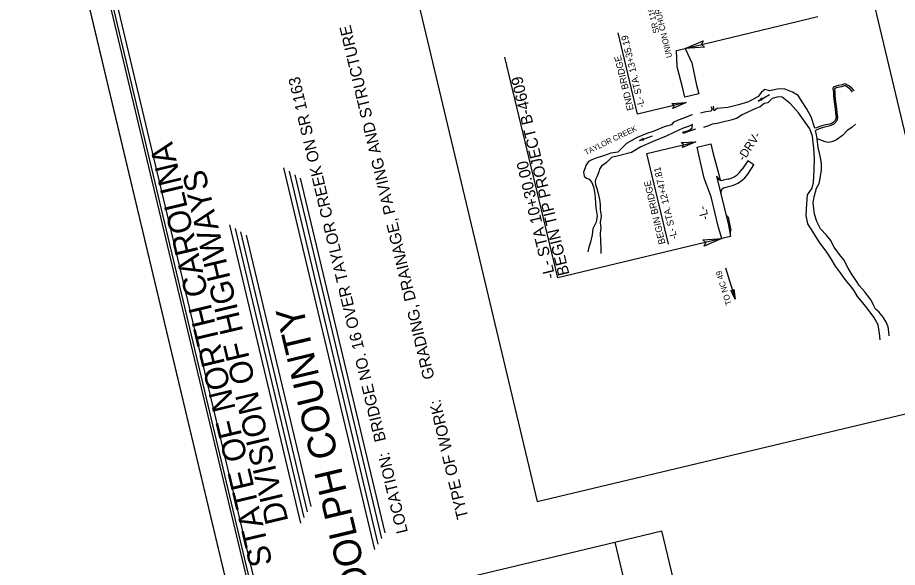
# Model space of a CAD drawing. Extents: x 1734738 to 1742883, y 698103 to 703125.
# Drawn here: x 1734738 to 1736650, y 699508 to 700702 of the extents above; entities that cross this region are included whole.
import ezdxf

# ---------------------------------------------------------------- set-up
doc = ezdxf.new("R2010")
doc.units = 0
for name, color, linetype in [('Default', 7, 'Continuous'), ('Exist Cultural Recreational Athletic Track', 7, 'Continuous'), ('Exist Map Preparation Border Sheet 1 CELL', 7, 'Continuous'), ('Exist Road Primary US Shield CELL', 7, 'Continuous'), ('Exist Road Primary US Structure Standard Bridge Number Label', 7, 'Continuous'), ('Exist Road Secondary Mileage Hundredths English Label', 7, 'Continuous'), ('Exist Road Secondary Structure Culvert Number Label', 7, 'Continuous'), ('Exist Road Secondary Structure Pipe Number Label', 7, 'Continuous'), ('Exist Road Secondary Type 41 Number Label', 7, 'Continuous'), ('Exist Road Secondary Type 41 SR Number Label', 7, 'Continuous'), ('Exist Road Secondary Type 51 Divided Label', 7, 'Continuous'), ('Exist Road Secondary Type 51 Undivided 3 Lane Attributed', 7, 'Continuous'), ('Level 54', 7, 'Continuous'), ('Level 55', 7, 'Continuous'), ('Level 57', 7, 'Continuous')]:
    doc.layers.add(name, color=color, linetype=linetype)

# ---------------------------------------------------------------- blocks, each defined once
blk = doc.blocks.new('EXIST HYDRO STREAM FLOW ARROW')
at = {"layer": 'Default'}
blk.add_line((0, 0), (0, 0), dxfattribs=at)
for points in [[(-0.1, 0.04575), (-0.07325, 0.03375), (-0.04475, 0.0245), (-0.0165, 0.01575), (0.01175, 0.0095), (0.041, 0.00475), (0.07075, 0.0015), (0.1, 0)], [(-0.1, -0.04575), (-0.07325, -0.03375), (-0.04475, -0.0245), (-0.0165, -0.01575), (0.01175, -0.0095), (0.041, -0.00475), (0.07075, -0.0015), (0.1, 0)]]:
    blk.add_lwpolyline(points, dxfattribs=at)

msp = doc.modelspace()

# ---------------------------------------------------------------- linework, layer by layer
at = {"layer": 'Exist Cultural Recreational Athletic Track'}
for p, q in [((1736188.7, 700634.5), (1736477, 700703.7)), ((1736085.2, 700491.6), (1736042.7, 700668.7)), ((1735912.1, 700136.2), (1735797, 700616)), ((1736190.9, 700516.9), (1736085.2, 700491.6)), ((1736152.6, 700209.8), (1736105.4, 700406.6)), ((1736268.4, 700221.7), (1735912.1, 700136.2)), ((1736276.5, 700158.5), (1736297.4, 700090.4))]:
    msp.add_line(p, q, dxfattribs=at)
at = {"layer": 'Exist Road Primary US Shield CELL'}
msp.add_lwpolyline([(1735867.2, 699650.6), (1736804.2, 699873.9), (1736485.1, 701212.6), (1735736.8, 701034.2), (1735787.7, 700820.7), (1735599, 700775.7)], close=True, dxfattribs=at)
at = {"layer": 'Exist Road Primary US Structure Standard Bridge Number Label'}
msp.add_line((1735518.8, 698102.6), (1734738, 701378.8), dxfattribs=at)
at = {"layer": 'Exist Road Secondary Mileage Hundredths English Label'}
for points in [[(1736556, 700542.9), (1736556, 700542.9), (1736551.3, 700547.4), (1736543.9, 700553.3), (1736537.8, 700557.2), (1736534.9, 700557.5), (1736529.4, 700555.7), (1736522, 700553.9), (1736516.7, 700553), (1736510.3, 700550.6), (1736509.5, 700546.8), (1736510.6, 700539.9), (1736510.7, 700532.1), (1736511.9, 700524.3), (1736513.2, 700513.6), (1736514.6, 700503.8), (1736515.4, 700494.8), (1736516.4, 700484.4), (1736514.8, 700477.9), (1736510.2, 700474.1), (1736503, 700470.4), (1736494.2, 700468.9), (1736485.6, 700466.5), (1736478.8, 700464.3), (1736473.7, 700462.3)], [(1736537.1, 700553.4), (1736537.1, 700553.4), (1736534.2, 700553.4), (1736528.2, 700550.9), (1736524.4, 700550.3), (1736520.4, 700549.7), (1736516.8, 700549.1), (1736513.8, 700547.7)], [(1736552.3, 700539.7), (1736547.5, 700545.2), (1736541.9, 700549.8), (1736537.1, 700553.4)], [(1736513.8, 700547.7), (1736513.3, 700545.1), (1736513.6, 700540.4), (1736513.9, 700532.6), (1736514.8, 700524.8), (1736516.1, 700514), (1736517.5, 700504.2), (1736518.3, 700494.8), (1736519.2, 700484.8), (1736518.2, 700477.7), (1736512.2, 700470.9), (1736503.8, 700466.9), (1736494.9, 700464.4), (1736486.3, 700462.4), (1736479.5, 700460.2)], [(1736473.7, 700462.3), (1736470.3, 700461.8)], [(1736479.5, 700460.2), (1736471.6, 700456.3)], [(1736559, 700470.1), (1736550.4, 700463.1), (1736540.9, 700456.4), (1736530.4, 700445.4), (1736517.1, 700435.9), (1736509.4, 700432.7), (1736500.5, 700430.6), (1736497.4, 700430.8), (1736493, 700432)], [(1736493, 700432), (1736475.1, 700438.1)]]:
    msp.add_lwpolyline(points, dxfattribs=at)
at = {"layer": 'Exist Road Secondary Structure Culvert Number Label'}
for p, q in [((1736105.4, 700406.6), (1736211.5, 700432)), ((1736035.6, 699562.3), (1736138, 699586.7)), ((1736326.6, 698795.4), (1736138, 699586.7))]:
    msp.add_line(p, q, dxfattribs=at)
msp.add_lwpolyline([(1735551.6, 698610.7), (1735363, 699402), (1736035.6, 699562.3), (1736224.2, 698771)], close=True, dxfattribs=at)
at = {"layer": 'Exist Road Secondary Structure Pipe Number Label'}
msp.add_lwpolyline([(1737609.2, 698627.6), (1736836.4, 701869.7), (1734783.7, 701380.5), (1735556.5, 698138.3)], close=True, dxfattribs=at)
at = {"layer": 'Exist Road Secondary Type 41 Number Label'}
for points in [[(1736230.5, 700637.1), (1736188.7, 700634.5), (1736227.4, 700651.2), (1736223.9, 700642.9)], [(1736159.5, 700514.9), (1736190.9, 700516.9), (1736161.9, 700504.3), (1736164.4, 700510.6)], [(1736180.2, 700430), (1736211.5, 700432), (1736182.5, 700419.4), (1736185.1, 700425.7)], [(1736226.6, 700219.2), (1736268.4, 700221.7), (1736229.7, 700205), (1736233.1, 700213.4)], [(1736294.6, 700111.2), (1736297.4, 700090.4), (1736287.7, 700109.1), (1736292, 700107.7)]]:
    msp.add_lwpolyline(points, close=True, dxfattribs=at)
at = {"layer": 'Exist Road Secondary Type 41 SR Number Label'}
msp.add_lwpolyline([(1734738, 701378.8), (1735518.8, 698102.6), (1737658.8, 698612.7), (1736878, 701888.9)], close=True, dxfattribs=at)
at = {"layer": 'Exist Road Secondary Type 51 Divided Label'}
for p, q in [((1735514.2, 699546.4), (1735316.7, 700375.2)), ((1735521.6, 699558.4), (1735328.8, 700367.8)), ((1735529.1, 699570.5), (1735340.8, 700360.4)), ((1735536.5, 699582.5), (1735352.9, 700353)), ((1735353.3, 699604), (1735199, 700251.3)), ((1735360.7, 699616), (1735211.1, 700243.9)), ((1735368.1, 699628), (1735223.1, 700236.5)), ((1735375.6, 699640.1), (1735235.1, 700229.1))]:
    msp.add_line(p, q, dxfattribs=at)
for points in [[(1734799.1, 701337.9), (1735485.4, 698458.5)], [(1734811.2, 701330.5), (1735469.6, 698567.9)]]:
    msp.add_lwpolyline(points, dxfattribs=at)
at = {"layer": 'Exist Road Secondary Type 51 Undivided 3 Lane Attributed'}
for p, q in [((1735435.9, 700215.7), (1735435.9, 700215.7)), ((1735385.8, 699956.9), (1735385.8, 699956.9))]:
    msp.add_line(p, q, dxfattribs=at)
at = {"layer": 'Level 54'}
for p, q in [((1736347, 700520), (1736372.1, 700534.8)), ((1736089.9, 700434.6), (1736117.2, 700444.9))]:
    msp.add_line(p, q, dxfattribs=at)
at = {"layer": 'Level 55'}
for points in [[(1736361.5, 700545.4), (1736354.5, 700539.6), (1736347.1, 700530.2), (1736326.5, 700519), (1736304.3, 700512.3), (1736280.9, 700506.6), (1736258.2, 700504.5), (1736251.2, 700499), (1736250, 700509.5)], [(1736470.3, 700461.8), (1736462.3, 700486.1), (1736452.3, 700504), (1736442.6, 700518.8), (1736433.9, 700532.5), (1736421.8, 700539.7), (1736403.6, 700546.6), (1736388.1, 700546.3), (1736372.5, 700542.2), (1736361.5, 700545.4)], [(1736229.3, 700463.7), (1736239.8, 700467.3), (1736248.2, 700470.7), (1736257.8, 700472.2), (1736275.2, 700476.7), (1736288.6, 700479.9), (1736299.8, 700483.4), (1736312.7, 700491.1), (1736322.8, 700495.6), (1736337.8, 700502.9), (1736351.4, 700508.8), (1736360.1, 700515.9), (1736368.8, 700517.5)], [(1736612.3, 700001.7), (1736610.6, 700015.4), (1736607.8, 700034.2), (1736598.6, 700051.2), (1736586.3, 700067.8), (1736571.7, 700085.6), (1736563.3, 700096.2), (1736555.3, 700109.9), (1736547.6, 700119.1), (1736536.4, 700132.8), (1736526.2, 700147.1), (1736515.3, 700162.1), (1736506, 700177.6), (1736496.3, 700192.3), (1736479.4, 700214.8), (1736466.7, 700235.3), (1736454.8, 700253.6), (1736451.4, 700271.5), (1736453.1, 700297.3), (1736454.3, 700316.4), (1736464.5, 700331.3), (1736467.7, 700343.8), (1736468.8, 700371.2), (1736469.6, 700395.8), (1736468, 700417.8), (1736465, 700444.4), (1736459.6, 700460), (1736445.6, 700479.9), (1736435.1, 700494.5), (1736417.3, 700514.6), (1736399.2, 700529), (1736390.5, 700529.6), (1736377.8, 700525.9), (1736368.8, 700517.5)], [(1736244.1, 700508.3), (1736246.9, 700503.1), (1736245.2, 700498.5), (1736233.4, 700496.7), (1736221.9, 700493.9)], [(1736203.4, 700490.2), (1736183.8, 700482.6), (1736173.5, 700479.1), (1736162.2, 700473.5), (1736158.9, 700468.5), (1736142.6, 700464.4), (1736119, 700454), (1736105.1, 700450.2), (1736084, 700441.5), (1736060.8, 700428.4)], [(1736203.2, 700490.1), (1736183.8, 700482.6), (1736173.5, 700479.1), (1736162.2, 700473.5), (1736158.9, 700468.5), (1736142.6, 700464.4), (1736119, 700454), (1736105.1, 700450.2), (1736084, 700441.5), (1736060.8, 700428.4)], [(1736210.7, 700459.6), (1736195.5, 700454.3), (1736185, 700450.2), (1736183.7, 700452.6), (1736195.7, 700456.3), (1736203.5, 700461.3), (1736203.5, 700464.5), (1736204.5, 700469.4), (1736197.5, 700465.5), (1736184, 700461.7), (1736165.3, 700452.7), (1736147.3, 700443.8), (1736118.7, 700432.5), (1736092.2, 700420.6), (1736072.1, 700408.9)], [(1736466.9, 700299.5), (1736468.8, 700312.3), (1736473.9, 700331.5), (1736479.4, 700341.5), (1736482.6, 700356.5), (1736485, 700371.2), (1736484.9, 700384), (1736482.6, 700398), (1736477.9, 700419.4), (1736475.1, 700438.1), (1736473.7, 700447), (1736471.6, 700456.3)], [(1736060.8, 700428.4), (1736042.5, 700409.6), (1736027.2, 700407.1), (1736010.9, 700401.4), (1735996.6, 700397.4), (1735985.6, 700392.9), (1735978.3, 700389), (1735972.8, 700380.3), (1735971, 700375.4), (1735967.9, 700365.8)], [(1736072.1, 700408.9), (1736043.8, 700401.1), (1736028.7, 700397.9), (1736017.7, 700387.2), (1736007.1, 700379), (1736002.3, 700372.1), (1736000.8, 700366.6)], [(1735967.9, 700365.8), (1735967.9, 700365.8), (1735968.6, 700361.5), (1735969.3, 700356.9), (1735974.1, 700353.1), (1735980.3, 700350.8), (1735985.9, 700343.3), (1735989.6, 700333.9), (1735991.4, 700322.5), (1735993.2, 700311.2), (1735993.6, 700297.6), (1735994.3, 700288.3), (1735995.6, 700280), (1735997, 700270.9), (1735995.4, 700257.6), (1735988.2, 700243), (1735986.7, 700229.9), (1735982.7, 700214.2), (1735979.5, 700202.7), (1735977, 700193.1)], [(1736000.8, 700366.6), (1736000.8, 700366.6), (1735997.6, 700357.5), (1735993.6, 700350.1), (1735992.9, 700345.2), (1735993.9, 700339.5), (1735996.4, 700330.4), (1735999.7, 700319.3), (1736002.3, 700306.4), (1736004, 700295.7), (1736004.2, 700284), (1736005.2, 700276.5), (1736006.2, 700270.3), (1736004.2, 700256.5), (1736005.2, 700244.1), (1736004.2, 700233.7), (1736004.4, 700216.2), (1736005.3, 700200.2), (1736005.2, 700189.4)], [(1736585.7, 700097.3), (1736585.7, 700097.3), (1736578.7, 700106.2), (1736567.6, 700119.4), (1736561.2, 700129.4), (1736551.3, 700142.9), (1736542.7, 700157.6), (1736533.3, 700175.7), (1736524.1, 700187.1), (1736512.6, 700203.2), (1736504.6, 700217.9), (1736496, 700229.3), (1736482.7, 700243.1), (1736474.9, 700258.6), (1736469.8, 700274.4), (1736467.9, 700286.3), (1736466.9, 700299.5)], [(1736632, 700010.6), (1736631.2, 700019.4), (1736629.5, 700030.1), (1736625, 700040.1), (1736618.7, 700051.2), (1736609.7, 700062.8), (1736602.1, 700068.6), (1736598.3, 700076), (1736592.4, 700088.3), (1736585.7, 700097.3)]]:
    msp.add_lwpolyline(points, dxfattribs=at)
at = {"layer": 'Level 57'}
for p, q in [((1736324.8, 700390.4), (1736312.7, 700372.4)), ((1736338.1, 700381.6), (1736324.8, 700390.4)), ((1736326, 700363.5), (1736338.1, 700381.6)), ((1736264.4, 700348.7), (1736256.9, 700357.1)), ((1736281.8, 700350.8), (1736271.4, 700348.3)), ((1736275.2, 700332.7), (1736285.6, 700335.2)), ((1736287, 700246.8), (1736283, 700268)), ((1736288.2, 700240.8), (1736287, 700246.8)), ((1736287.7, 700240.1), (1736288.2, 700240.8))]:
    msp.add_line(p, q, dxfattribs=at)
for points in [[(1736188.7, 700634.5), (1736203, 700603.4), (1736213.5, 700554.6), (1736218, 700535.9), (1736188, 700528.6), (1736183.5, 700547.3), (1736183.5, 700547.3), (1736171.4, 700594.7), (1736171, 700595.8), (1736169.9, 700630)], [(1736268.4, 700221.7), (1736261.3, 700245.7), (1736245.2, 700312.1), (1736229.7, 700352.8), (1736218.4, 700403.8), (1736214.3, 700420.3), (1736244.3, 700427.6), (1736248.8, 700408.9), (1736248.8, 700408.9), (1736261.6, 700360.6), (1736264.5, 700348.6), (1736264.4, 700348.7), (1736256.9, 700357.1), (1736265.4, 700321.9), (1736282.7, 700250.9), (1736282.7, 700250.9), (1736287.4, 700226.3)]]:
    msp.add_lwpolyline(points, close=True, dxfattribs=at)
for points in [[(1736256.9, 700357.1), (1736265.4, 700321.9), (1736266.3, 700318.2)], [(1736276.8, 700275), (1736282.7, 700250.9), (1736286.2, 700232.6)]]:
    msp.add_lwpolyline(points, dxfattribs=at)
for centre, radius, start, end in [((1736269.5, 700401.3), 52, 283.6519, 326.2194), ((1736269.5, 700401.3), 68, 283.6519, 326.2194), ((1736268.5, 700359.9), 12, 193.6519, 249.527), ((1736268.5, 700359.9), 12, 193.6519, 283.6519), ((1736278, 700321.1), 12, 103.6519, 193.6519), ((1736286.5, 700277.3), 10, 193.6519, 249.4963), ((1736296, 700234.5), 10, 146.4515, 190.9706)]:
    msp.add_arc(centre, radius, start, end, dxfattribs=at)

# ---------------------------------------------------------------- block references
at = {"layer": 'Level 54', "yscale": 49.99999999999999}
for p, xscale, rotation in [((1736351.3, 700522.5), 49.999999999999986, -149.1137213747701), ((1736093.5, 700435.9), 50, -159.12784213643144)]:
    msp.add_blockref('EXIST HYDRO STREAM FLOW ARROW', p, dxfattribs=dict(at, xscale=xscale, rotation=rotation))

# ---------------------------------------------------------------- texts
at = {"layer": 'Exist Cultural Recreational Athletic Track'}
for s, height, rotation, p in [('UNION CHURCH RD', 12.844, 103.4845, (1736160.4, 700615.9)), ('SR 1163', 12.84, 103.4845, (1736132.3, 700669.1)), ('-L- STA. 13+35.19', 14.679, 103.4845, (1736100.9, 700507.9)), ('END BRIDGE', 14.68, 103.4845, (1736076.9, 700501.6)), ('BEGIN TIP PROJECT B-4609', 24.771, 103.4845, (1735937.2, 700144.5)), ('-DRV-', 18.35, 57.1569, (1736316.6, 700388.7)), ('-L- STA 10+30.00', 24.771, 103.4845, (1735906.8, 700137.3)), ('-L- STA. 12+47.81', 14.679, 103.4845, (1736171.6, 700222.1)), ('BEGIN BRIDGE', 14.679, 103.4845, (1736145.9, 700211.1)), ('-L-', 18.35, 103.4797, (1736240.2, 700265)), ('TO NC 49', 12.84, 107.0772, (1736289.7, 700079.3))]:
    msp.add_text(s, height=height, rotation=rotation, dxfattribs=at).set_placement(p)
at = {"layer": 'Exist Map Preparation Border Sheet 1 CELL'}
for s, height, p in [('GRADING, DRAINAGE, PAVING AND STRUCTURE ', 25, (1735644.3, 699919.2)), ('BRIDGE NO. 16 OVER TAYLOR CREEK ON SR 1163 ', 25, (1735538.8, 699783.5)), ('       RANDOLPH COUNTY       ', 60, (1735579.7, 699143.2))]:
    msp.add_text(s, height=height, rotation=103.4059, dxfattribs=at).set_placement(p)
at = {"layer": 'Exist Road Secondary Type 51 Divided Label'}
for s, height, p in [('STATE OF NORTH CAROLINA', 50, (1735292.2, 699515.8)), ('DIVISION OF HIGHWAYS', 50, (1735326.7, 699608.1)), ('TYPE OF WORK:', 25, (1735717.6, 699615.8)), ('LOCATION: ', 25, (1735586.2, 699584.5))]:
    msp.add_text(s, height=height, rotation=103.4059, dxfattribs=at).set_placement(p)
at = {"layer": 'Level 54'}
msp.add_text('TAYLOR CREEK', height=11.999, rotation=25.8618, dxfattribs=at).set_placement((1735973.1, 700402.7))

doc.saveas('drawing.dxf')
